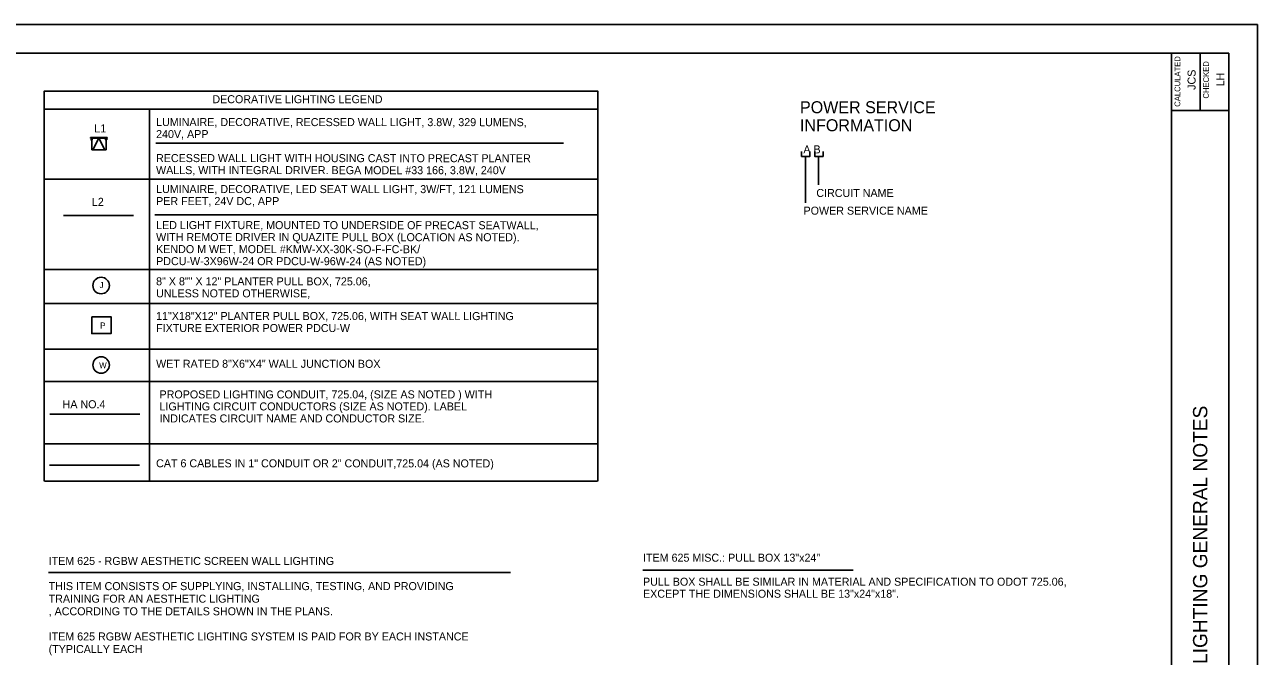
# Model space of a CAD drawing. Extents: x 0 to 127, y 0 to 26.
# Drawn here: x 12.44 to 34, y 10.96 to 22 of the extents above; entities that cross this region are included whole.
import ezdxf

# ---------------------------------------------------------------- set-up
doc = ezdxf.new("R2010")
doc.units = 0
for name, color, linetype in [('Default', 7, 'Continuous'), ('LT_P_Circuit3', 7, 'Continuous'), ('LT_P_Conduit', 7, 'Continuous'), ('LT_P_Control_Center', 7, 'Continuous'), ('LT_P_Luminaires', 7, 'Continuous'), ('LT_P_PullBox', 7, 'Continuous'), ('LT_P_Text', 7, 'Continuous'), ('SH_Border', 7, 'Continuous'), ('SH_Cut_Line', 7, 'Continuous'), ('SH_Data', 7, 'Continuous'), ('SH_Text', 7, 'Continuous')]:
    doc.layers.add(name, color=color, linetype=linetype)

msp = doc.modelspace()

# ---------------------------------------------------------------- linework, layer by layer
at = {"layer": 'Default'}
for p, q in [((26.099, 19.696), (26.099, 18.885)), ((26.327, 19.696), (26.327, 19.198))]:
    msp.add_line(p, q, dxfattribs=at)
for points in [[(26.031, 19.781), (26.031, 19.696), (26.176, 19.696), (26.176, 19.782)], [(26.261, 19.781), (26.261, 19.696), (26.406, 19.696), (26.406, 19.782)]]:
    msp.add_lwpolyline(points, dxfattribs=at)
at = {"layer": 'LT_P_Circuit3'}
for p, q in [((13.598, 20.028), (13.595, 20.025)), ((13.595, 20.025), (13.889, 20.025)), ((13.595, 20.018), (13.595, 20.025)), ((13.595, 20.018), (13.889, 20.018)), ((13.886, 20.028), (13.598, 20.028)), ((13.601, 20.018), (13.601, 20.017)), ((13.601, 20.017), (13.607, 20.017)), ((13.605, 19.987), (13.605, 20.016)), ((13.606, 19.985), (13.614, 19.985)), ((13.607, 20.017), (13.607, 20.018)), ((13.607, 20.017), (13.877, 20.017)), ((13.61, 20.028), (13.61, 20.029)), ((13.619, 20.029), (13.61, 20.029)), ((13.61, 20.028), (13.61, 20.028)), ((13.619, 20.028), (13.61, 20.028)), ((13.614, 19.985), (13.624, 19.985)), ((13.617, 19.985), (13.617, 19.836)), ((13.617, 19.836), (13.617, 19.83)), ((13.628, 20.029), (13.619, 20.029)), ((13.628, 20.028), (13.619, 20.028)), ((13.625, 20.016), (13.625, 20)), ((13.626, 19.994), (13.626, 19.987)), ((13.628, 20.029), (13.628, 20.028)), ((13.628, 20.028), (13.628, 20.028)), ((13.857, 20.028), (13.857, 20.029)), ((13.866, 20.029), (13.857, 20.029)), ((13.857, 20.028), (13.857, 20.028)), ((13.866, 20.028), (13.857, 20.028)), ((13.857, 20.028), (13.857, 20.028)), ((13.859, 19.987), (13.859, 19.994)), ((13.86, 20), (13.86, 20.016)), ((13.861, 19.985), (13.871, 19.985)), ((13.875, 20.029), (13.866, 20.029)), ((13.875, 20.028), (13.866, 20.028)), ((13.867, 19.836), (13.867, 19.985)), ((13.867, 19.836), (13.867, 19.83)), ((13.871, 19.985), (13.878, 19.985)), ((13.875, 20.029), (13.875, 20.028)), ((13.875, 20.028), (13.875, 20.028)), ((13.877, 20.018), (13.877, 20.017)), ((13.877, 20.017), (13.884, 20.017)), ((13.88, 20.016), (13.88, 19.987)), ((13.884, 20.017), (13.884, 20.018)), ((13.889, 20.025), (13.886, 20.028)), ((13.889, 20.018), (13.889, 20.025)), ((13.617, 19.83), (13.617, 19.817)), ((13.621, 19.814), (13.634, 19.814)), ((13.621, 19.814), (13.634, 19.814)), ((13.634, 19.814), (13.654, 19.814)), ((13.654, 19.814), (13.83, 19.814)), ((13.83, 19.814), (13.851, 19.814)), ((13.851, 19.814), (13.864, 19.814)), ((13.851, 19.814), (13.864, 19.814)), ((13.867, 19.83), (13.867, 19.817)), ((13.12, 18.663), (14.348, 18.663))]:
    msp.add_line(p, q, dxfattribs=at)
msp.add_lwpolyline([(13.626, 20.017), (13.626, 20.017), (13.626, 20.017)], dxfattribs=at)
msp.add_lwpolyline([(13.742, 20.017), (13.847, 19.814), (13.638, 19.814)], close=True, dxfattribs=at)
for centre, radius, start, end in [((13.603, 20.016), 0.00159, 0.0029, 90.0029), ((13.606, 19.987), 0.00159, 180.0029, 270.0029), ((13.626, 20.016), 0.00146, 96.7256, 185.4281), ((13.624, 20.015), 0.000511, 37.0433, 89.0203), ((13.624, 19.987), 0.00159, 270.0029, 0.0029), ((13.627, 20.015), 0.00195, 104.9066, 165.0994), ((13.657, 20.002), 0.032, 182.5857, 193.6227), ((13.859, 20.017), 0.00068, 101.478, 158.1162), ((13.858, 20.015), 0.00195, 14.9067, 75.099), ((13.843, 19.999), 0.0166, 341.3562, 2.5913), ((13.861, 19.987), 0.00159, 180.0029, 270.0029), ((13.86, 20.015), 0.000508, 90.802, 143.1449), ((13.878, 19.987), 0.00159, 270.0029, 0.0029), ((13.882, 20.016), 0.00159, 90.0029, 180.0029), ((13.621, 19.817), 0.00313, 180.0029, 270.0029), ((13.864, 19.817), 0.00313, 270.0029, 0.0029)]:
    msp.add_arc(centre, radius, start, end, dxfattribs=at)
at = {"layer": 'LT_P_Conduit'}
for p, q in [((12.783, 20.522), (22.468, 20.522)), ((12.783, 19.297), (22.468, 19.297)), ((12.783, 17.719), (22.468, 17.719))]:
    msp.add_line(p, q, dxfattribs=at)
msp.add_lwpolyline([(12.783, 14.021), (12.783, 20.835), (22.468, 20.835), (22.468, 14.021)], dxfattribs=at)
at = {"layer": 'LT_P_Control_Center'}
msp.add_line((12.879, 14.303), (14.452, 14.303), dxfattribs=at)
at = {"layer": 'LT_P_Luminaires'}
msp.add_lwpolyline([(13.618, 16.895), (13.956, 16.895), (13.956, 16.599), (13.618, 16.599)], close=True, dxfattribs=at)
for centre in [(13.781, 17.44), (13.781, 16.051)]:
    msp.add_circle(centre, 0.144, dxfattribs=at)
at = {"layer": 'LT_P_PullBox'}
msp.add_line((12.881, 15.189), (14.459, 15.189), dxfattribs=at)
at = {"layer": 'LT_P_Text'}
for p, q in [((14.626, 20.522), (14.626, 16.522)), ((14.736, 19.928), (21.865, 19.928)), ((14.721, 18.678), (22.468, 18.678)), ((12.783, 17.125), (22.468, 17.125)), ((14.626, 17.125), (14.626, 14.021)), ((12.792, 15.761), (22.46, 15.761)), ((12.783, 14.675), (22.468, 14.675)), ((12.792, 14.021), (22.46, 14.021)), ((23.255, 12.462), (26.931, 12.462))]:
    msp.add_line(p, q, dxfattribs=at)
msp.add_lwpolyline([(22.468, 16.327), (12.783, 16.327)], dxfattribs=at)
for centre, start, end in [((12.792, 15.769), 180, 270), ((22.46, 15.769), 270, 0)]:
    msp.add_arc(centre, 0.00833, start, end, dxfattribs=at)
at = {"layer": 'SH_Border'}
for p, q in [((32.5, 0.5), (32.5, 21.5)), ((33, 21.5), (33, 20.5)), ((32.5, 20.5), (33.5, 20.5))]:
    msp.add_line(p, q, dxfattribs=at)
msp.add_lwpolyline([(2, 21.5), (33.5, 21.5), (33.5, 0.5), (2, 0.5)], close=True, dxfattribs=at)
at = {"layer": 'SH_Cut_Line'}
msp.add_lwpolyline([(0, 0), (34, 0), (34, 22), (0, 22)], close=True, dxfattribs=at)
at = {"layer": 'SH_Text'}
msp.add_line((20.938, 12.424), (12.863, 12.424), dxfattribs=at)

# ---------------------------------------------------------------- texts
at = {"layer": 'LT_P_Conduit'}
for s, rotation, p in [('DECORATIVE LIGHTING LEGEND', 360, (15.726, 20.627)), ('LUMINAIRE, DECORATIVE, RECESSED WALL LIGHT, 3.8W, 329 LUMENS, ', 359.9775, (14.742, 20.228)), ('L1', 359.9775, (13.661, 20.117)), ('240V, APP', 359.9775, (14.742, 20.018)), ('RECESSED WALL LIGHT WITH HOUSING CAST INTO PRECAST PLANTER ', 359.9775, (14.741, 19.598)), ('WALLS, WITH INTEGRAL DRIVER. BEGA MODEL #33 166, 3.8W, 240V', 359.9775, (14.741, 19.388)), ('LUMINAIRE, DECORATIVE, LED SEAT WALL LIGHT, 3W/FT, 121 LUMENS ', 359.9775, (14.742, 19.057)), ('L2', 359.9775, (13.619, 18.833)), ('PER FEET, 24V DC, APP', 359.9775, (14.742, 18.847)), ('LED LIGHT FIXTURE, MOUNTED TO UNDERSIDE OF PRECAST SEATWALL, ', 359.9775, (14.742, 18.427)), ('WITH REMOTE DRIVER IN QUAZITE PULL BOX (LOCATION AS NOTED). ', 359.9775, (14.742, 18.217)), ('KENDO M WET, MODEL #KMW-XX-30K-SO-F-FC-BK/ ', 359.9775, (14.742, 18.007)), ('PDCU-W-3X96W-24 OR PDCU-W-96W-24 (AS NOTED)', 359.9775, (14.742, 17.797)), ('8" X 8"" X 12" PLANTER PULL BOX, 725.06, ', 359.9775, (14.742, 17.444)), ('UNLESS NOTED OTHERWISE, ', 359.9775, (14.742, 17.234)), ('11"X18"X12" PLANTER PULL BOX, 725.06, WITH SEAT WALL LIGHTING ', 359.9775, (14.742, 16.838)), ('FIXTURE EXTERIOR POWER PDCU-W', 359.9775, (14.742, 16.628)), ('WET RATED 8"X6"X4" WALL JUNCTION BOX ', 359.9775, (14.742, 16.003)), ('CAT 6 CABLES IN 1" CONDUIT OR 2" CONDUIT,725.04 (AS NOTED) ', 359.9775, (14.742, 14.263))]:
    msp.add_text(s, height=0.14, rotation=rotation, dxfattribs=at).set_placement(p)
for s, p in [('A B', (26.061, 19.75)), ('CIRCUIT NAME', (26.288, 18.988)), ('POWER SERVICE NAME', (26.064, 18.679))]:
    msp.add_text(s, height=0.14, dxfattribs=at).set_placement(p)
at = {"layer": 'LT_P_Luminaires'}
for s, p in [('J', (13.752, 17.395)), ('P', (13.764, 16.689)), ('W', (13.746, 15.995))]:
    msp.add_text(s, height=0.105, rotation=360, dxfattribs=at).set_placement(p)
at = {"layer": 'LT_P_Text'}
for s, height, p in [('POWER SERVICE', 0.21, (26.002, 20.452)), ('INFORMATION', 0.21, (26.002, 20.137)), ('PROPOSED LIGHTING CONDUIT, 725.04, (SIZE AS NOTED ) WITH ', 0.14, (14.802, 15.467)), ('HA NO.4', 0.14, (13.107, 15.295)), ('LIGHTING CIRCUIT CONDUCTORS (SIZE AS NOTED). LABEL ', 0.14, (14.802, 15.257)), ('INDICATES CIRCUIT NAME AND CONDUCTOR SIZE.', 0.14, (14.802, 15.047)), ('ITEM 625 MISC.: PULL BOX 13"x24"', 0.14, (23.257, 12.613)), ('PULL BOX SHALL BE SIMILAR IN MATERIAL AND SPECIFICATION TO ODOT 725.06, ', 0.14, (23.257, 12.193)), ('EXCEPT THE DIMENSIONS SHALL BE 13"x24"x18".', 0.14, (23.257, 11.983))]:
    msp.add_text(s, height=height, dxfattribs=at).set_placement(p)
at = {"layer": 'SH_Data'}
for s, height, p in [('CALCULATED', 0.1, (32.652, 20.565)), ('CHECKED', 0.1, (33.152, 20.708)), ('JCS', 0.14, (32.92, 20.86)), ('LH', 0.14, (33.42, 20.922)), (' ODOT - DECORATIVE LIGHTING GENERAL NOTES   ', 0.25, (33.125, 7.204))]:
    msp.add_text(s, height=height, rotation=90, dxfattribs=at).set_placement(p)
at = {"layer": 'SH_Text'}
for s, p in [('ITEM 625 - RGBW AESTHETIC SCREEN WALL LIGHTING ', (12.863, 12.556)), ('THIS ITEM CONSISTS OF SUPPLYING, INSTALLING, TESTING, AND PROVIDING ', (12.863, 12.116)), ('TRAINING FOR AN AESTHETIC LIGHTING ', (12.863, 11.896)), (', ACCORDING TO THE DETAILS SHOWN IN THE PLANS. ', (12.863, 11.676)), ('ITEM 625 RGBW AESTHETIC LIGHTING SYSTEM IS PAID FOR BY EACH INSTANCE ', (12.863, 11.236)), ('(TYPICALLY EACH ', (12.863, 11.016))]:
    msp.add_text(s, height=0.14, rotation=360, dxfattribs=at).set_placement(p)

doc.saveas('drawing.dxf')
